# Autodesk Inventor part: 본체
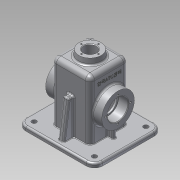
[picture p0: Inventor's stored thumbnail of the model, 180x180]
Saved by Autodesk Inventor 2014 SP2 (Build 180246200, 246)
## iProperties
Created: 2016-08
Part Number: 본체
Material: 알루미늄 6061
Document SubType Name: Modeling
Designer: 402-32
Density: 2.71 g/cm^3
Appearance: 알루미늄 - 평지
Mass: 798.505 g
Surface Area: 917.253 cm^2
Volume: 294.651 cm^3
Author: 402-32
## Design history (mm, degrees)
sketch "스케치1"
  geometry: L1 (-60, -52.5)-(60, -52.5); L2 (60, -52.5)-(60, 52.5); L3 (60, 52.5)-(-60, 52.5); L4 (-60, 52.5)-(-60, -52.5); L5 (-60, -52.5)-(60, 52.5); L6 (60, -52.5)-(-60, 52.5); 1 further point
  constraints: 12 end point, 2 midpoint, 2 parallel, 1 horizontal, 1 perpendicular
  dimensions: "d0" = 120 distance of L3.end L2.end; "d1" = 105 distance of L2.end L1.end
extrude "돌출1" new body sketch "스케치1" distance "d2" = 3; taper "d3" = 0 deg
sketch "스케치2"
  geometry: L1 (-65, -57.5)-(65, -57.5); L2 (65, -57.5)-(65, 57.5); L3 (65, 57.5)-(-65, 57.5); L4 (-65, 57.5)-(-65, -57.5); L5 (-65, -57.5)-(65, 57.5); L6 (65, -57.5)-(-65, 57.5); 1 further point
  constraints: 12 end point, 2 midpoint, 2 parallel, 1 horizontal, 1 perpendicular
  dimensions: "d4" = 130 distance of L3.end L2.end; "d5" = 115 distance of L2.end L1.end
extrude "돌출2" join sketch "스케치2" distance "d6" = 7; taper "d7" = 0 deg
sketch "스케치3"
  geometry: L1 (-32.5, -32.5)-(32.5, -32.5); L2 (32.5, -32.5)-(32.5, 32.5); L3 (32.5, 32.5)-(-32.5, 32.5); L4 (-32.5, 32.5)-(-32.5, -32.5); L5 (-32.5, -32.5)-(32.5, 32.5); L6 (32.5, -32.5)-(-32.5, 32.5); 1 further point
  constraints: 12 end point, 2 midpoint, 2 parallel, 1 horizontal, 1 perpendicular
  dimensions: "d8" = 65 distance of L3.end L2.end; "d9" = 65 distance of L2.end L1.end
extrude "돌출3" join sketch "스케치3" distance "d10" = 100; taper "d11" = 0 deg
sketch "스케치4"
  geometry: C1 r 20 at (0, 0); 1 further point
  constraints: 1 centre point, 1 coincident
  dimensions: "d12" = 40 diameter of C1
extrude "돌출4" join sketch "스케치4" distance "d13" = 10; taper "d14" = -7 deg
sketch "스케치5"
  geometry: L1 (27.5, -27.5)-(-27.5, -27.5); L2 (-27.5, -27.5)-(-27.5, 27.5); L3 (-27.5, 27.5)-(27.5, 27.5); L4 (27.5, 27.5)-(27.5, -27.5); L5 (27.5, -27.5)-(-27.5, 27.5); L6 (-27.5, -27.5)-(27.5, 27.5); 1 further point
  constraints: 12 end point, 2 midpoint, 2 parallel, 1 horizontal, 1 perpendicular
  dimensions: "d15" = 55 distance of L2.end L3.end; "d16" = 55 distance of L1.end L2.end
extrude "돌출5" cut sketch "스케치5" distance "d17" = 105; taper "d18" = 0 deg
sketch "스케치6"
  geometry: L1 (0, 65)-(0, 0) reference; L2 (-100, 0)-(-100, 65) reference; C1 r 27.5 at (-45, 32.5); 2 further points
  constraints: 1 centre point, 1 horizontal alignment, 1 midpoint
  dimensions: "d19" = 55 diameter of C1; "d20" = 45 distance from line of L1 C1.centre
extrude "돌출6" join sketch "스케치6" distance "d21" = 15; taper "d22" = 0 deg
sketch "스케치7"
  geometry: L1 (0, 65)-(0, 0) reference; L2 (0, 0)-(-100, 0) reference; L3 (0, 35.5)-(-17.664, 35.5); L4 (0, 29.5)-(-17.664, 29.5); L5 (-17.5, 32.5)-(0, 32.5); A1 r 27.5 centre (-45, 32.5) between (-17.664, 35.5) and (-17.664, 29.5) reference; 1 further point
  constraints: 6 end point, 3 point on circle, 2 parallel, 2 point on line, 1 midpoint, 1 other
  dimensions: "d23" = 6 distance between parallel lines of L3 L4
extrude "돌출7" join sketch "스케치7" distance "d24" = 10; taper "d25" = 0 deg
hole "구멍1" diameter "d28" = 21; stored, may be unused: countersink angle "d32" = 90 deg, drill point angle "d34" = 0 deg; dims "d26" = 10, "d27" = 10, "d29" = 6, "d30" = 4, "d31" = 2, "d33" = 8
hole "구멍2" diameter "d37" = 30; stored, may be unused: countersink angle "d41" = 90 deg, drill point angle "d43" = 0 deg; dims "d35" = 10, "d36" = 10, "d38" = 6, "d39" = 35, "d40" = 17, "d42" = 8
hole "구멍3" diameter "d46" = 35; stored, may be unused: countersink angle "d50" = 90 deg, drill point angle "d52" = 0 deg; dims "d44" = 10, "d45" = 10, "d47" = 6, "d48" = 35, "d49" = 17, "d51" = 17
sketch "스케치8"
  geometry: L1 (32.5, 10)-(32.5, 110) reference; L2 (57.5, 10)-(-57.5, 10) reference; L3 (32.5, 70)-(41.068, 70); L4 (41.068, 70)-(49.5, 10); L5 (57.5, 3)-(57.5, 10) reference; L6 (52.5, 0)-(-52.5, 0) reference; 1 further point
  constraints: 4 end point, 2 point on line, 1 parallel
  dimensions: "d53" = 8 distance of L2.start L4.end; "d54" = 8 deg angle of L5 L4; "d55" = 70 distance from line of L6 L3.end
extrude "돌출8" join sketch "스케치8" stored distance "d56" = 10; taper "d57" = 0 deg
sketch "스케치9"
  geometry: L1 (-10, 13.728)-(-10, 51.272) reference; A1 r 27.5 centre (55, 32.5) between (82.336, 35.5) and (82.336, 29.5) reference; 2 further points
  constraints: 1 horizontal alignment, 1 other
  dimensions: "d58" = 26 distance from line of L1 point (16, 32.5)
feature "엠보싱1" sketch "스케치9" dims "d8" = 65, "d9" = 65, "d59" = 0.5, "d60" = 0
fillet "모깎기1" dims "d61" = 9, "d62" = 14
hole "구멍4" diameter "d65" = 8; stored, may be unused: countersink angle "d69" = 90 deg, drill point angle "d71" = 0 deg; dims "d63" = 10, "d64" = 10, "d66" = 6, "d67" = 35, "d68" = 17, "d70" = 17
hole "구멍5" diameter "d74" = 8; stored, may be unused: countersink angle "d78" = 90 deg, drill point angle "d80" = 0 deg; dims "d72" = 10, "d73" = 10, "d75" = 6, "d76" = 35, "d77" = 17, "d79" = 17
hole "구멍6" diameter "d83" = 8; stored, may be unused: countersink angle "d87" = 90 deg, drill point angle "d89" = 0 deg; dims "d81" = 10, "d82" = 10, "d84" = 6, "d85" = 35, "d86" = 17, "d88" = 17
hole "구멍7" diameter "d92" = 8; stored, may be unused: countersink angle "d96" = 90 deg, drill point angle "d98" = 0 deg; dims "d90" = 10, "d91" = 10, "d93" = 6, "d94" = 35, "d95" = 17, "d97" = 17
sketch "스케치10"
  geometry: C1 r 17.5 at (0, 0) reference; 2 further points
  dimensions: "d99" = 21 distance of C1.centre point (0, 21)
hole "구멍8" sketch "스케치10" at (0, 21) diameter "d100" = 3.242; stored, may be unused: countersink angle "d104" = 90 deg, drill point angle "d106" = 118 deg; dims "d101" = 8, "d102" = 35, "d103" = 17, "d105" = 10
sketch "스케치11"
  geometry: C1 r 10.5 at (0, 0) reference; 1 further point
  dimensions: "d110" = 14.5 distance of C1.centre point (0, 14.5)
hole "구멍9" sketch "스케치11" at (0, 14.5) diameter "d111" = 2.459; stored, may be unused: countersink angle "d115" = 90 deg, drill point angle "d117" = 118 deg; dims "d112" = 7, "d113" = 35, "d114" = 17, "d116" = 9
fillet "모깎기2" dims "d121" = 3, "d122" = 8
fillet "모깎기3" dims "d123" = 3
fillet "모깎기4" dims "d124" = 3
fillet "모깎기5" dims "d125" = 3
fillet "모깎기6" dims "d126" = 1
fillet "모깎기7" dims "d127" = 0.3
chamfer "모따기1" distance "d128" = 1; stored, may be unused: second distance "d129" = 2, angle "d130" = 45 deg
node "솔리드1"
mirror "대칭1"
mirror "대칭2"
pattern_circular "원형 패턴1" dims angle "d108" = 360 deg
mirror "대칭3"
pattern_circular "원형 패턴2" dims angle "d119" = 360 deg
